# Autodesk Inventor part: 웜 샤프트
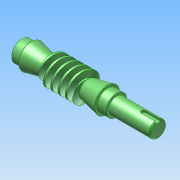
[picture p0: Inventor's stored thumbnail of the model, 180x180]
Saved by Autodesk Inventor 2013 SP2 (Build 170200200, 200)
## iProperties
Created: 2025-06
Part Number: 웜 샤프트
Material: Generic
Document SubType Name: Modeling
Designer: a
Density: 1 g/cm^3
Author: a
변환 표준: STEP AP214IS
전처리기: Build: 200, Release: 2013 SP2 Update 6 - Date: Thu 07/17/2014
전송 단위: 밀리미터
불확실성: 0.01
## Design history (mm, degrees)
node "웜 샤프트1"
body "Solid1"
node "기준1"
